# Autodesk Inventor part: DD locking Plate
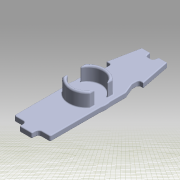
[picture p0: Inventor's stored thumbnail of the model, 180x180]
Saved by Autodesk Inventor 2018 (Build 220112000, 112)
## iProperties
Created: 2013-06
Part Number: DD locking Plate
Material: Generic
Description: STEP AP214
Document SubType Name: Modeling
Designer: johne
Appearance: Generic
Title: Baseplate insert.STEP
Author: Asher
Revision Number: ANY
Sending System: SolidWorks 2013
Preprocessor: SwSTEP 2.0
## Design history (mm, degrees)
feature "Body-Move_Copy1"
body "Solid1"
